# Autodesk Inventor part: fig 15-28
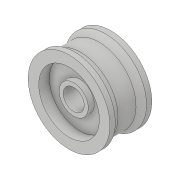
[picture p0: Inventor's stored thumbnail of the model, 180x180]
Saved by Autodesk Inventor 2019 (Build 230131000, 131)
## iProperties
Created: 2018-03
Part Number: fig 15-28
Material: Generic
Document SubType Name: Modeling
Designer: CADCIM 00
Density: 1 g/cm^3
Appearance: Default
Author: CADCIM 00
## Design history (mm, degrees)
sketch "Sketch1"
  geometry: L1 (3.327, 5.31)-(3.327, -4.99); L2 (3.327, -4.99)-(4.606, -4.99); L3 (4.606, -4.99)-(4.606, -3.071); L4 (4.606, -3.071)-(9.597, -3.071); L5 (9.597, -3.071)-(9.597, -6.462); L6 (9.597, -6.462)-(12.924, -6.462); L7 (12.924, -6.462)-(12.924, -4.766); L8 (12.924, -4.766)-(11.708, -2.687); L9 (11.708, -2.687)-(11.708, 0.16); L10 (11.708, 0.16)-(3.327, 0.16); L11 (3.327, 5.31)-(4.606, 5.31); L12 (4.606, 5.31)-(4.606, 3.391); L13 (4.606, 3.391)-(9.597, 3.391); L14 (9.597, 3.391)-(9.597, 6.782); L15 (9.597, 6.782)-(12.924, 6.782); L16 (12.924, 6.782)-(12.924, 5.086); L17 (12.924, 5.086)-(11.708, 3.007); L18 (11.708, 3.007)-(11.708, 0.16); L19 (0, 7.901)-(0, -9.532); 1 further point
  constraints: 38 end point, 7 symmetric about line, 6 perpendicular, 2 vertical, 1 midpoint, 1 parallel
revolve "Revolution1" sketch "Sketch1" stored, may be unused: angle "d0" = 90 deg
body "Solid1"
